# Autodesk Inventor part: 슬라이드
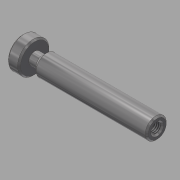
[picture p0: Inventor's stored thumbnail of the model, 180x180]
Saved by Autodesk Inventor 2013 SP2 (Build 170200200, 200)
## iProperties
Created: 2015-12
Part Number: 슬라이드
Document SubType Name: Modeling
Designer: mdu
Density: 8.08 g/cm^3
Material: 스테인리스강
Author: mdu
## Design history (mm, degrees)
sketch "스케치1"
  geometry: L1 (-45, 0)-(45, 0); L2 (-45, 0)-(-45, 10.5); L3 (-45, 10.5)-(-37, 10.5); L4 (-37, 10.5)-(-37, 4); L5 (-37, 4)-(-32, 4); L6 (-32, 4)-(-29, 7); L7 (-29, 7)-(45, 7); L8 (45, 7)-(45, 0); 2 further points
  constraints: 16 end point, 4 parallel, 2 perpendicular, 1 coincident, 1 horizontal, 1 midpoint
  dimensions: "d0" = 90 distance of L1.start L1.end; "d1" = 21 diameter of L3 L1; "d2" = 14 diameter of L7 L1; "d3" = 8 diameter of L5 L1; "d4" = 8 distance of L2.end L3.end; "d5" = 5 distance of L4.end L5.end; "d6" = 135 deg angle of L6 L5
revolve "회전1" sketch "스케치1" stored, may be unused: angle "d7" = 90 deg
chamfer "모따기1" distance "d8" = 1; stored, may be unused: second distance "d9" = 2, angle "d10" = 45 deg
hole "구멍1" diameter "d13" = 6.647; stored, may be unused: countersink angle "d17" = 90 deg, drill point angle "d19" = 118 deg; dims "d11" = 10, "d12" = 10, "d14" = 9, "d15" = 4, "d16" = 2, "d18" = 12
chamfer "모따기2" distance "d20" = 1; stored, may be unused: second distance "d21" = 2, angle "d22" = 45 deg
node "솔리드1"
